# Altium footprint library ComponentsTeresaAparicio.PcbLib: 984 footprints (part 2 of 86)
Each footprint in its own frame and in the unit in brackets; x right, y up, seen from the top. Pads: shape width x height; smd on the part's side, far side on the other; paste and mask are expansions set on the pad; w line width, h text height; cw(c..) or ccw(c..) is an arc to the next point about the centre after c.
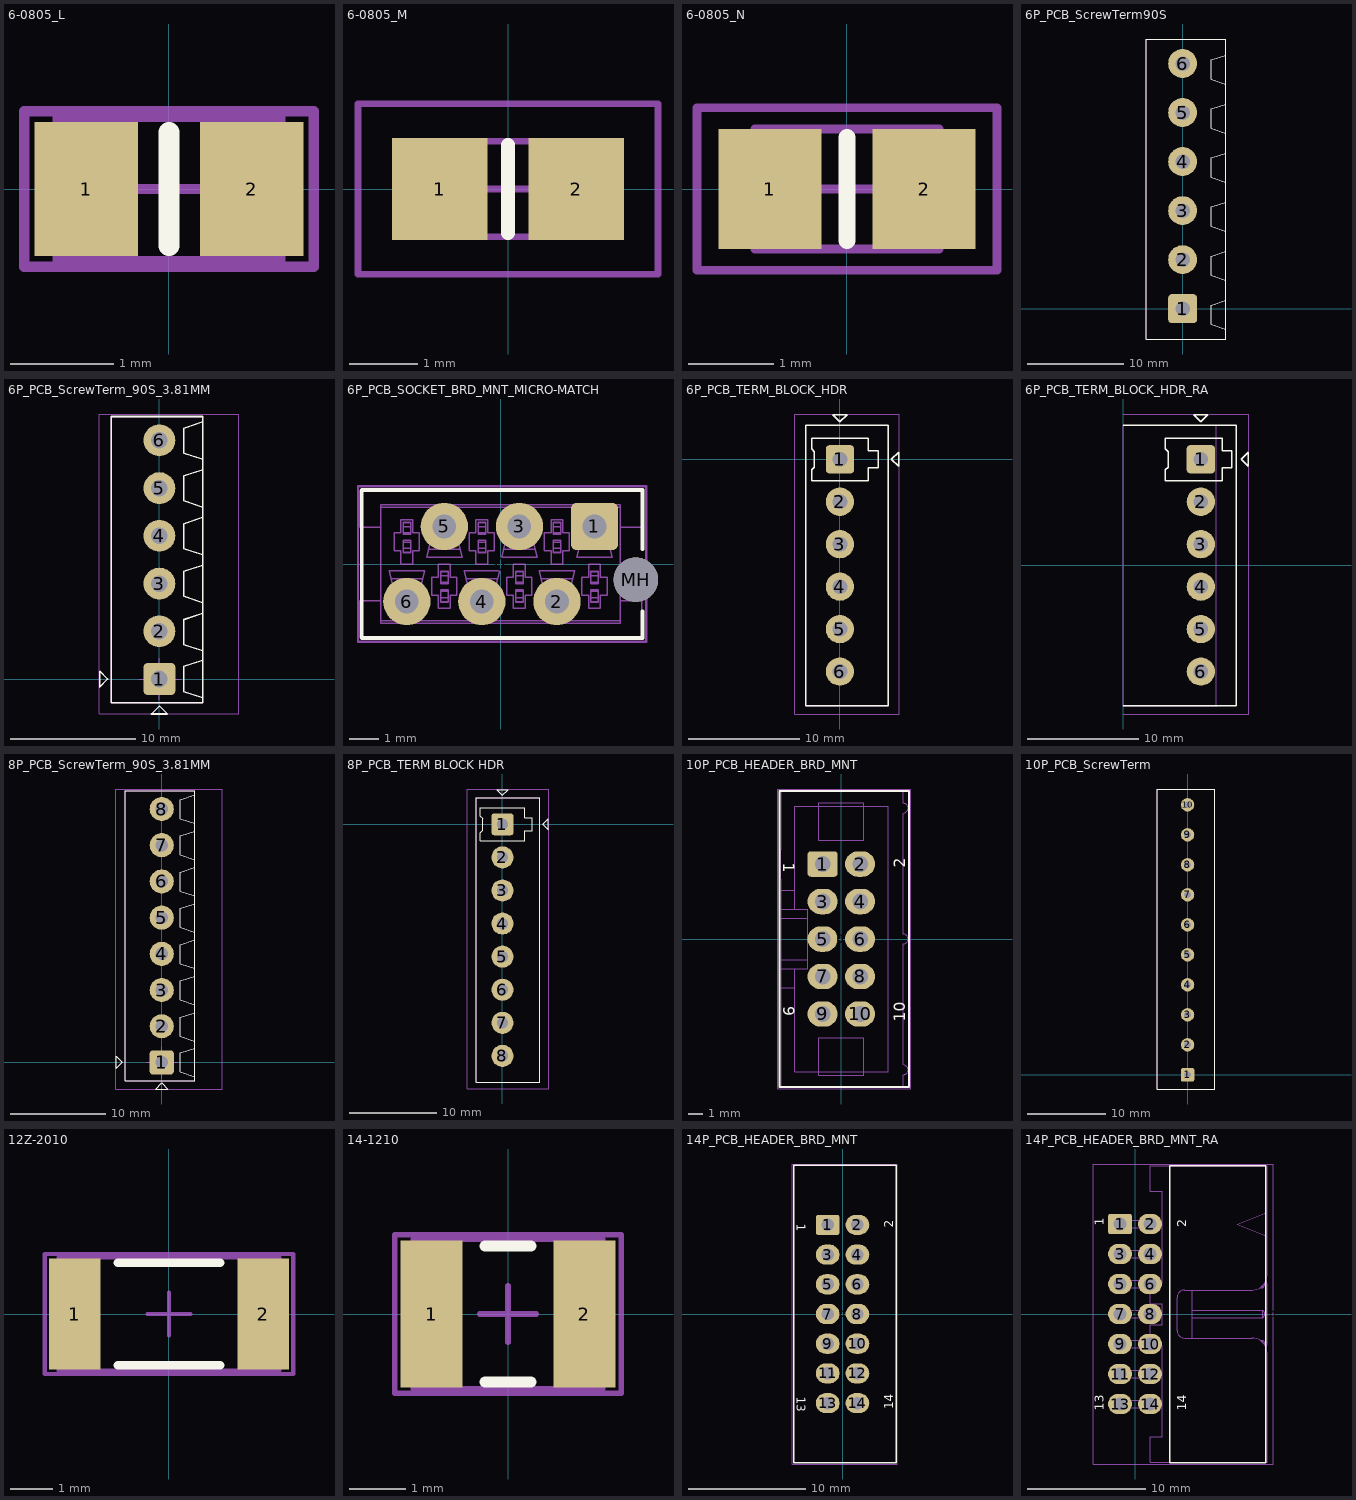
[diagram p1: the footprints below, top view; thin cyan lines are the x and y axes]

## 6-0805_L [mm] "Chip Resistor, Body 2.0x1.2mm, IPC High Density"
height 0.7
pads (2):
  rect 1x1.3 smd: 1(-0.8,0) 2(0.8,0)
Top Overlay:
  lines w0.2: 0,-0.55 0,0.55
Mechanical 13:
  lines w0.1: -1.075,-0.7 1.075,-0.7 1.075,0.7 -1.075,0.7 -1.075,-0.7
Mechanical 15:
  lines w0.1: -0.5,0 0.5,0 ; 0,-0.5 0,0.5 ; -1.4,-0.75 1.4,-0.75 1.4,0.75 -1.4,0.75 -1.4,-0.75
3D body: height 0.7, standoff 0, extent -1.075,-0.7 1.075,0.7

## 6-0805_M [mm] "Chip Resistor, Body 2.0x1.2mm, IPC Low Density"
height 0.7
pads (2):
  rect 1.4x1.5 smd: 1(-1,0) 2(1,0)
Top Overlay:
  lines w0.2: 0,-0.65 0,0.65
Mechanical 13:
  lines w0.1: -1.075,-0.7 1.075,-0.7 1.075,0.7 -1.075,0.7 -1.075,-0.7
Mechanical 15:
  lines w0.1: -0.5,0 0.5,0 ; 0,-0.5 0,0.5 ; -2.2,-1.25 2.2,-1.25 2.2,1.25 -2.2,1.25 -2.2,-1.25
3D body: height 0.7, standoff 0, extent -1.075,-0.7 1.075,0.7

## 6-0805_N [mm] "Chip Resistor, Body 2.0x1.2mm, IPC Medium Density"
height 0.7
pads (2):
  rect 1.2x1.4 smd: 1(-0.9,0) 2(0.9,0)
Top Overlay:
  lines w0.2: 0,-0.6 0,0.6
Mechanical 13:
  lines w0.1: -1.075,-0.7 1.075,-0.7 1.075,0.7 -1.075,0.7 -1.075,-0.7
Mechanical 15:
  lines w0.1: -0.5,0 0.5,0 ; 0,-0.5 0,0.5 ; -1.75,-0.95 1.75,-0.95 1.75,0.95 -1.75,0.95 -1.75,-0.95
3D body: height 0.7, standoff 0, extent -1.075,-0.7 1.075,0.7

## 6P_PCB_ScrewTerm90S [mm] "TERM BLOCK 6POS SIDE ENT STACKABLE 5.08MM"
height 10
pads (6):
  rrect25% 3x3 hole 1.5: 1(0,0)
  round 3 hole 1.5: 2(0,5.08) 3(0,10.16) 4(0,15.24) 5(0,20.32) 6(0,25.4)
Top Overlay:
  lines w0.127: 4.45,-2.124 2.95,-1.624 2.95,0.376 4.45,0.876 ; 4.45,2.956 2.95,3.456 2.95,5.456 4.45,5.956 ; 4.45,8.036 2.95,8.536 2.95,10.536 4.45,11.036 ; 4.45,13.116 2.95,13.616 2.95,15.616 4.45,16.116 ; 4.45,18.196 2.95,18.696 2.95,20.696 4.45,21.196 ; 4.45,23.276 2.95,23.776 2.95,25.776 4.45,26.276 ; -3.75,-3.14 -3.75,27.94 4.45,27.94 4.45,-3.14 -3.75,-3.14
Mechanical 13:
  lines w0.076: -3.75,-3.14 -3.75,27.94 4.45,27.94 4.45,-3.14 -3.75,-3.14
3D body: height 10.02, standoff -2.58, extent -3.75,-3.14 4.45,27.94

## 6P_PCB_ScrewTerm_90S_3.81MM [mil] "TERM BLOCK 6POS SIDE ENT STACKABLE 3.81MM"
height 334.65
pads (6):
  rrect25% 100x100 hole 52: 1(0,0)
  round 100 hole 52: 2(0,150) 3(0,300) 4(0,450) 5(0,600) 6(0,750)
Top Overlay:
  lines w5: 135.83,-59.06 76.78,-39.37 76.78,39.37 135.83,59.06 ; 135.83,88.58 76.78,108.27 76.78,187.01 135.83,206.69 ; 135.83,240 76.78,259.69 76.78,338.43 135.83,358.11 ; 135.83,390 76.78,409.69 76.78,488.43 135.83,508.11 ; 135.83,540 76.78,559.68 76.78,638.43 135.83,658.11 ; 135.83,690 76.78,709.68 76.78,788.43 135.83,808.11 ; -188,-25 -163,0 -188,25 -188,-25 ; -151.57,-75 -151.57,825 135.83,825 135.83,-75 -151.57,-75 ; -25,-110 25,-110 0,-85 -25,-110
Mechanical 13:
  lines w3: -151.57,-75 135.83,-75 135.83,825 -151.57,825 -151.57,-75
Mechanical 14:
  lines w3: -65,0 65,0 ; 0,-65 0,65 ; -190,-110 -190,832.88 250,832.88 250,-110 -190,-110
3D body: height 335.25, standoff -137.2, extent -151.57,-75 135.83,825

## 6P_PCB_SOCKET_BRD_MNT_MICRO-MATCH [mm] "SOCKET MICRO-MATCH BRD MNT 6POS 2.54MM"
height 4.2
pads (8):
  round 1.016 on Mech14: 0(0,0)
  rrect25% 1.6x1.6 hole 0.8: 1(3.175,1.27)
  round 1.6 hole 0.8: 2(1.905,-1.27) 3(0.635,1.27) 4(-0.635,-1.27) 5(-1.905,1.27) 6(-3.175,-1.27)
  round 1.5 hole 1.5 unplated: MH(4.575,-0.53)
Top Overlay:
  lines w0.127: 4.8,-1.6 4.8,-2.5 -4.7,-2.5 -4.7,2.5 4.8,2.5 4.8,0.5
Mechanical 13:
  drawing of 280 lines, arcs and shapes, not listed
Mechanical 14:
  lines w0.076: -4.827,-2.627 -4.827,2.627 4.927,2.627 4.927,-2.627 -4.827,-2.627
3D body: height 4, standoff -3, extent -4.775,-2.5 4.775,2.5

## 6P_PCB_TERM_BLOCK_HDR [mil] "TERM BLOCK HDR 6POS 3.81MM"
height 362.2
pads (6):
  rrect25% 100x100 hole 52: 1(0,0)
  round 100 hole 52: 2(0,-150) 3(0,-300) 4(0,-450) 5(0,-600) 6(0,-750)
Top Overlay:
  lines w5: -120,-870 170,-870 170,120 -120,120 -120,-870 ; -100,-75 100,-75 100,-30 135,-30 135,30 100,30 100,75 -100,75 -100,37.5 -90,27.5 -90,-27.5 -100,-37.5 -100,-75 ; -25,157 0,132 25,157 -25,157 ; 182,0 207,25 207,-25 182,0
Mechanical 13:
  lines w3: -120,-870 -120,120 170,120 170,-870 -120,-870
Mechanical 14:
  lines w3: -160,-900 210,-900 210,160 -160,160 -160,-900
3D body: height 362.8, standoff -133.26, extent -118.11,-870.07 167.33,120.08
3D body: height 362.2, standoff 0, extent -120,-870 170,120

## 6P_PCB_TERM_BLOCK_HDR_RA [mil] "TERM BLOCK HDR 6POS 3.81MM RIGHT-ANGLE"
height 362.2
pads (6):
  rrect25% 100x100 hole 52: 1(275,375)
  round 100 hole 52: 2(275,225) 3(275,75) 4(275,-75) 5(275,-225) 6(275,-375)
Top Overlay:
  lines w5: 0,-495 400,-495 400,495 0,495 ; 150,300 350,300 350,345 385,345 385,405 350,405 350,450 150,450 150,412.5 160,402.5 160,347.5 150,337.5 150,300 ; 250,532 275,507 300,532 250,532 ; 417,375 442,400 442,350 417,375
Mechanical 13:
  lines w3: 0,-495 0,495 330,495 330,-495 0,-495
Mechanical 14:
  lines w3: 0,-525 445,-525 445,535 0,535
3D body: height 288, standoff -133.26, extent -40,-495.08 322.2,495.08

## 8P_PCB_ScrewTerm_90S_3.81MM [mil] "TERM BLOCK 8POS SIDE ENT STACKABLE 3.81MM"
height 334.65
pads (8):
  rrect25% 100x100 hole 52: 1(0,0)
  round 100 hole 52: 2(0,150) 3(0,300) 4(0,450) 5(0,600) 6(0,750) 7(0,900) 8(0,1050)
Top Overlay:
  lines w5: 135.83,-59.06 76.78,-39.37 76.78,39.37 135.83,59.06 ; 135.83,88.58 76.78,108.27 76.78,187.01 135.83,206.69 ; 135.83,240 76.78,259.69 76.78,338.43 135.83,358.11 ; 135.83,390 76.78,409.69 76.78,488.43 135.83,508.11 ; 135.83,540 76.78,559.68 76.78,638.43 135.83,658.11 ; 135.83,690 76.78,709.68 76.78,788.43 135.83,808.11 ; 135.83,840 76.78,859.68 76.78,938.43 135.83,958.11 ; 135.83,990 76.78,1009.68 76.78,1088.43 135.83,1108.11 ; -188,-25 -163,0 -188,25 -188,-25 ; -151.57,-75 -151.57,1125 135.83,1125 135.83,-75 -151.57,-75 ; -25,-110 25,-110 0,-85 -25,-110
Mechanical 13:
  lines w3: -151.57,-75 135.83,-75 135.83,1125 -151.57,1125 -151.57,-75
Mechanical 14:
  lines w3: -65,0 65,0 ; 0,-65 0,65 ; -190,-110 -190,1132.88 250,1132.88 250,-110 -190,-110
3D body: height 335.25, standoff -137.2, extent -151.57,-75 135.83,1125

## 8P_PCB_TERM BLOCK HDR [mil] "TERM BLOCK HDR 8POS 3.81MM"
height 362.2
pads (8):
  rrect25% 100x100 hole 52: 1(0,0)
  round 100 hole 52: 2(0,-150) 3(0,-300) 4(0,-450) 5(0,-600) 6(0,-750) 7(0,-900) 8(0,-1050)
Top Overlay:
  lines w5: -120,-1170 170,-1170 170,120 -120,120 -120,-1170 ; -100,-75 100,-75 100,-30 135,-30 135,30 100,30 100,75 -100,75 -100,37.5 -90,27.5 -90,-27.5 -100,-37.5 -100,-75 ; -25,157 0,132 25,157 -25,157 ; 182,0 207,25 207,-25 182,0
Mechanical 13:
  lines w3: -120,-1170 -120,120 170,120 170,-1170 -120,-1170
Mechanical 14:
  lines w3: -160,-1200 210,-1200 210,160 -160,160 -160,-1200
3D body: height 362.8, standoff -133.26, extent -118.11,-1170.07 167.33,120.08
3D body: height 362.2, standoff 0, extent -120,-1170 170,120

## 10P_PCB_HEADER_BRD_MNT [mil] "HEADER BRD MNT 10POS 2.54MM"
height 390
pads (11):
  round 40 on Mech14: 0(0,0)
  rrect25% 80x68 hole 42: 1(-50,200)
  oval 80x68 hole 42: 2(50,200) 3(-50,100) 4(50,100) 5(-50,0) 6(50,0) 7(-50,-100) 8(50,-100) 9(-50,-200) 10(50,-200)
Top Overlay:
  lines w5: -165,-395 180,-395 180,395 -165,395 -165,-395
  text "9" at -155,-179 h30
  text "10" at 170,-220.28 h30
  text "1" at -155,203.57 h30
  text "2" at 170,190 h30
Mechanical 13:
  drawing of 154 lines, arcs and shapes, not listed
Mechanical 14:
  lines w3: -170,-400 185,-400 185,400 -170,400 -170,-400
3D body: height 390, standoff -120, extent -161.99,-393.99 178.01,394.01

## 10P_PCB_ScrewTerm [mm] "TERM BLOCK 10POS SIDE ENT 3.81MM"
height 8.5
pads (10):
  rrect25% 1.7x1.7 hole 0.85: 1(0,0)
  round 1.7 hole 0.85: 2(0,3.81) 3(0,7.62) 4(0,11.43) 5(0,15.24) 6(0,19.05) 7(0,22.86) 8(0,26.67) 9(0,30.48) 10(0,34.29)
Top Overlay:
  lines w0.127: -3.85,-1.8 3.45,-1.8 3.45,36.3 -3.85,36.3 -3.85,-1.8
Mechanical 13:
  lines w0.076: -3.85,-1.8 -3.85,36.3 3.45,36.3 3.45,-1.8 -3.85,-1.8
3D body: height 8.5, standoff 0, extent -3.85,-1.8 3.45,36.3

## 12Z-2010 [mm] "Chip Resistor, Body 5.0x2.5mm, IPC High Density"
height 0.9
pads (2):
  rect 1.2x2.6 smd: 1(-2.2,0) 2(2.2,0)
Top Overlay:
  lines w0.2: -1.2,-1.2 1.2,-1.2 ; -1.2,1.2 1.2,1.2
Mechanical 13:
  lines w0.1: -2.575,-1.325 2.575,-1.325 2.575,1.325 -2.575,1.325 -2.575,-1.325
Mechanical 15:
  lines w0.1: -0.5,0 0.5,0 ; 0,-0.5 0,0.5 ; -2.9,-1.4 2.9,-1.4 2.9,1.4 -2.9,1.4 -2.9,-1.4
3D body: height 0.9, standoff 0, extent -2.575,-1.325 2.575,1.325

## 14-1210 [mm] "Chip Resistor, Body 3.2x2.5mm, IPC High Density"
height 0.9
pads (2):
  rect 1.1x2.6 smd: 1(-1.35,0) 2(1.35,0)
Top Overlay:
  lines w0.2: -0.4,-1.2 0.4,-1.2 ; -0.4,1.2 0.4,1.2
Mechanical 13:
  lines w0.1: -1.675,-1.32 -1.675,1.32 1.675,1.32 1.675,-1.32 -1.675,-1.32
Mechanical 15:
  lines w0.1: -0.5,0 0.5,0 ; 0,-0.5 0,0.5 ; -2,-1.4 -2,1.4 2,1.4 2,-1.4 -2,-1.4
3D body: height 0.9, standoff 0, extent -1.675,-1.32 1.675,1.32

## 14P_PCB_HEADER_BRD_MNT [mil] "HEADER BRD MNT 14POS 2.54MM"
height 390
pads (15):
  round 40 on Mech14: 0(0,0)
  rrect25% 80x68 hole 42: 1(-50,300)
  oval 80x68 hole 42: 2(50,300) 3(-50,200) 4(50,200) 5(-50,100) 6(50,100) 7(-50,0) 8(50,0) 9(-50,-100) 10(50,-100) 11(-50,-200) 12(50,-200) 13(-50,-300) 14(50,-300)
Top Overlay:
  lines w5: -165,-500 -165,500 180,500 180,-500 -165,-500
  text "2" at 170,290 h30
  text "1" at -155,303.57 h30
  text "14" at 170,-320.28 h30
  text "13" at -155,-279 h30
Mechanical 14:
  lines w3: -170,-505 -170,505 185,505 185,-505 -170,-505
3D body: height 390, standoff -120, extent -161.99,-493.99 178.01,494.01

## 14P_PCB_HEADER_BRD_MNT_RA [mil] "HEADER BRD MNT R/A 14POS 2.54MM"
height 338
pads (16):
  round 40 on Mech14: 0(0,0) 0(460,0)
  rrect25% 80x68 hole 42: 1(-50,300)
  oval 80x68 hole 42: 2(50,300) 3(-50,200) 4(50,200) 5(-50,100) 6(50,100) 7(-50,0) 8(50,0) 9(-50,-100) 10(50,-100) 11(-50,-200) 12(50,-200) 13(-50,-300) 14(50,-300)
Top Overlay:
  lines w5: 115,-495 435,-495 435,495 115,495 115,-495
  text "13" at -105,-323 h30
  text "14" at 170,-323 h30
  text "1" at -105,295 h30
  text "2" at 170,290 h30
Mechanical 13:
  lines w1.97: -17.5,-312.25 -17.5,-287.75 ; -17.5,-212.25 -17.5,-187.75 ; -17.5,-112.25 -17.5,-87.75 ; -17.5,-12.25 -17.5,12.25 ; -17.5,87.75 -17.5,112.25 ; -17.5,187.75 -17.5,212.25 ; -17.5,287.75 -17.5,312.25 ; 50,-87.75 -62.5,-87.75 -62.5,-112.25 90,-112.25 ; 50,87.75 -62.5,87.75 -62.5,112.25 90,112.25 ; 90,-312.25 -62.5,-312.25 -62.5,-287.75 90,-287.75 ; 90,-212.25 -62.5,-212.25 -62.5,-187.75 90,-187.75 ; 90,-12.25 -62.5,-12.25 -62.5,12.25 90,12.25 ; 90,187.75 -62.5,187.75 -62.5,212.25 90,212.25 ; 90,287.75 -62.5,287.75 -62.5,312.25 90,312.25 ; 190,-80 190,80 ; 190,-12.25 425,-12.25 ; 190,12.25 425,12.25 ; 416.74,-87.75 425,-87.75 ; 416.74,87.75 425,87.75 ; 425,-94.29 425,-87.75 ; 425,94.29 425,87.75 ; 433,-104.25 433,-95.75 425,-87.75 ; 433,104.25 433,95.75 425,87.75 ; 437.7,-115 ccw(c390,-100) 440,-100 440,100 ccw(c390,100) 437.7,115 ; 440,260 340,300 440,340 ; 425,-12.25 433,-4.25 433,4.25 425,12.25 ; 425,-12.25 425,12.25 ; 50,-494 50,-409 90,-409 90,-105 50,-105 50,-35 90,-35 90,35 50,35 50,105 90,105 90,409 50,409 50,494 440,494 440,130 cw(c390,130) 390,80 165,80 ccw(c165,55) 140,55 140,-55 ccw(c165,-55) 165,-80 390,-80 cw(c390,-130) 440,-130 440,-494 50,-494
Mechanical 14:
  lines w3: -140,-500 460,-500 460,500 -140,500 -140,-500
3D body: height 340, standoff -112, extent -62.49,-493.99 440.01,494.01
